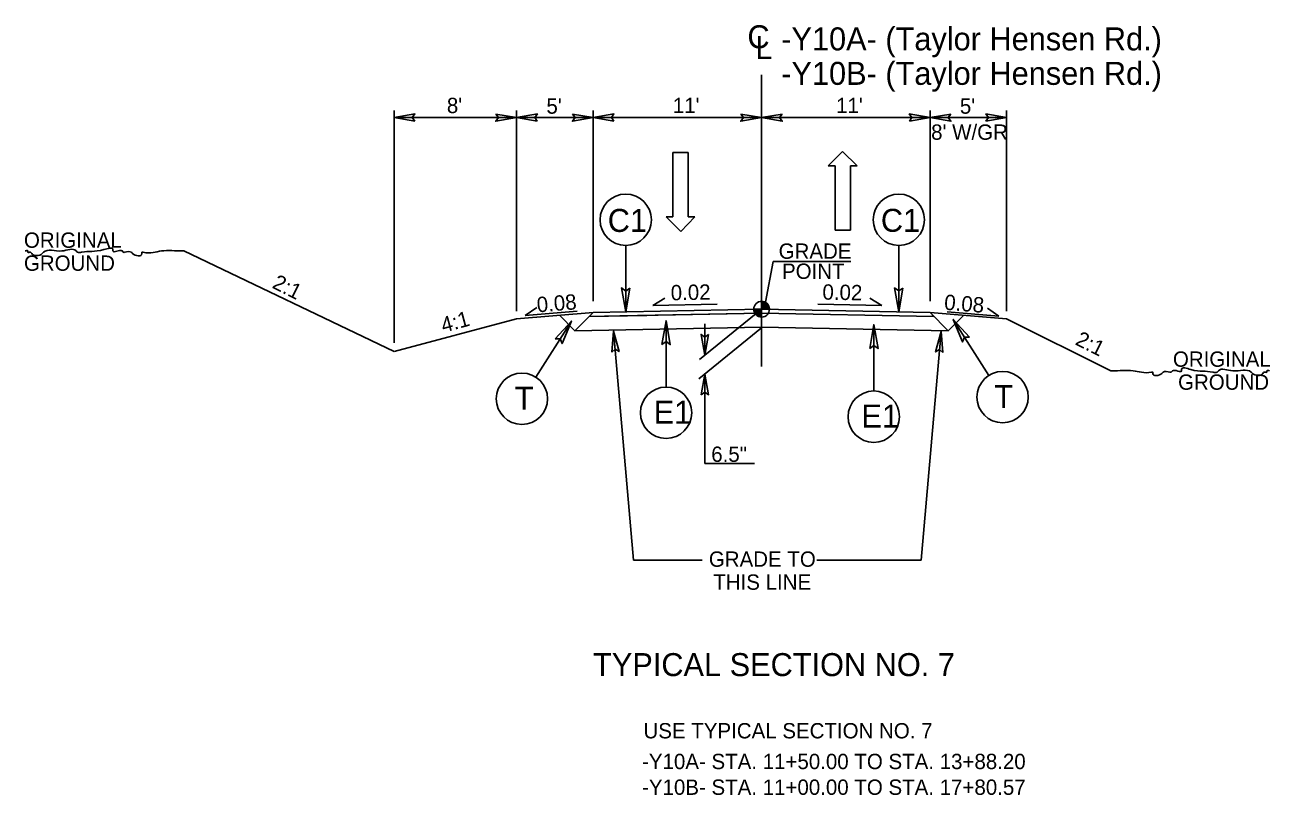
# Model space of a CAD drawing. Extents: x 18938 to 19565, y 6931 to 7973.
# Drawn here: x 19397.7 to 19479, y 7533.7 to 7584 of the extents above; entities that cross this region are included whole.
import ezdxf

# ---------------------------------------------------------------- set-up
doc = ezdxf.new("R2010")
doc.units = 0
for name, color, linetype in [('Old_Level_11', 7, 'Continuous'), ('Old_Level_2', 7, 'Continuous'), ('Prop Pavement Schedule Description CELL', 7, 'Continuous'), ('Prop Shade Medium', 7, 'Continuous'), ('Prop Terminator CELL', 7, 'Continuous'), ('Sheet Data Field CELL', 7, 'Continuous'), ('Sheet Plot Border Outside CELL', 7, 'Continuous'), ('Sheet Typical CELL', 7, 'Continuous'), ('Typical Curb CELL', 7, 'Continuous'), ('Typical Detail Wedge1 CELL', 7, 'Continuous'), ('Typical Detail Wedge2 CELL', 7, 'Continuous'), ('Typical Detail Wedge3 CELL', 7, 'Continuous'), ('Typical Hinge Slope Arterial CELL', 7, 'Continuous'), ('Typical Shoulder Slope Information CELL', 7, 'Continuous'), ('Typical Terminator CELL', 7, 'Continuous'), ('Typical Text General CELL', 7, 'Continuous'), ('Typical Text Grade Point CELL', 7, 'Continuous'), ('Typical Text ID Circle CELL', 7, 'Continuous'), ('Typical Text Label CELL', 7, 'Continuous')]:
    doc.layers.add(name, color=color, linetype=linetype)

msp = doc.modelspace()

# ---------------------------------------------------------------- linework, layer by layer
at = {"layer": 'Prop Pavement Schedule Description CELL'}
for p, q in [((19429.776, 7564.789), (19434.776, 7565.189)), ((19433.585, 7563.998), (19432.571, 7565.012)), ((19433.585, 7563.998), (19434.776, 7565.189)), ((19438.276, 7565.009), (19434.521, 7564.934)), ((19434.776, 7565.189), (19445.776, 7565.409)), ((19436.776, 7564.979), (19445.776, 7565.159)), ((19456.776, 7565.189), (19445.776, 7565.409)), ((19445.776, 7565.159), (19457.031, 7564.934)), ((19461.776, 7564.789), (19456.776, 7565.189)), ((19457.966, 7563.998), (19456.776, 7565.189)), ((19457.966, 7563.998), (19458.981, 7565.012)), ((19468.577, 7561.388), (19461.776, 7564.789)), ((19433.585, 7563.998), (19445.776, 7564.242)), ((19438.276, 7564.096), (19438.276, 7564.092)), ((19457.966, 7563.998), (19445.776, 7564.242)), ((19453.276, 7564.096), (19453.276, 7564.092))]:
    msp.add_line(p, q, dxfattribs=at)
at = {"layer": 'Prop Shade Medium'}
for p in [(19408.043, 7569.209), (19429.776, 7564.789)]:
    msp.add_line(p, (19421.776, 7562.64), dxfattribs=at)
at = {"layer": 'Sheet Data Field CELL'}
for points in [[(19423.126, 7577.681), (19421.776, 7577.914), (19423.133, 7578.154), (19422.961, 7577.914)], [(19428.426, 7578.146), (19429.776, 7577.914), (19428.418, 7577.674), (19428.591, 7577.914)], [(19431.126, 7577.681), (19429.776, 7577.914), (19431.133, 7578.154), (19430.961, 7577.914)], [(19433.426, 7578.146), (19434.776, 7577.914), (19433.418, 7577.674), (19433.591, 7577.914)], [(19436.126, 7577.681), (19434.776, 7577.914), (19436.133, 7578.154), (19435.961, 7577.914)], [(19444.416, 7578.146), (19445.766, 7577.914), (19444.409, 7577.674), (19444.581, 7577.914)], [(19447.116, 7578.146), (19445.766, 7577.914), (19447.124, 7577.674), (19446.951, 7577.914)], [(19455.426, 7577.681), (19456.776, 7577.914), (19455.418, 7578.154), (19455.591, 7577.914)], [(19458.126, 7578.146), (19456.776, 7577.914), (19458.133, 7577.674), (19457.961, 7577.914)], [(19460.426, 7577.681), (19461.776, 7577.914), (19460.418, 7578.154), (19460.591, 7577.914)], [(19435.998, 7562.614), (19436.113, 7563.979), (19436.469, 7562.647), (19436.215, 7562.799)], [(19457.606, 7562.588), (19457.492, 7563.953), (19457.134, 7562.621), (19457.389, 7562.772)], [(19442.299, 7563.754), (19442.067, 7562.404), (19441.827, 7563.762), (19442.067, 7563.589)], [(19441.835, 7559.831), (19442.067, 7561.181), (19442.307, 7559.823), (19442.067, 7559.996)]]:
    msp.add_lwpolyline(points, close=True, dxfattribs=at)
at = {"layer": 'Sheet Typical CELL'}
for p, q in [((19421.776, 7578.374), (19421.776, 7563.209)), ((19421.776, 7577.914), (19429.776, 7577.914)), ((19429.776, 7578.374), (19429.776, 7565.286)), ((19429.776, 7577.914), (19434.776, 7577.914)), ((19434.776, 7578.374), (19434.776, 7565.929)), ((19456.776, 7577.914), (19434.776, 7577.914)), ((19456.776, 7578.374), (19456.776, 7565.929)), ((19461.776, 7577.914), (19456.776, 7577.914)), ((19461.776, 7578.374), (19461.776, 7565.286)), ((19445.776, 7565.409), (19441.721, 7562.124)), ((19437.405, 7549.027), (19436.113, 7563.979)), ((19445.776, 7564.185), (19441.671, 7560.86)), ((19442.067, 7564.448), (19442.067, 7562.404)), ((19456.187, 7549.027), (19457.492, 7563.953)), ((19442.067, 7561.181), (19442.067, 7555.343)), ((19442.067, 7555.343), (19445.319, 7555.343)), ((19437.405, 7549.027), (19441.893, 7549.027)), ((19449.371, 7549.027), (19456.187, 7549.027))]:
    msp.add_line(p, q, dxfattribs=at)
at = {"layer": 'Typical Curb CELL'}
for points in [[(19397.678, 7569.209), (19397.85, 7569.209), (19397.85, 7569.124), (19398.021, 7569.124), (19398.107, 7569.038), (19398.792, 7569.038), (19398.877, 7569.124), (19400.077, 7569.209), (19401.019, 7569.209), (19401.105, 7569.124), (19401.362, 7569.124), (19402.818, 7569.295), (19403.417, 7569.295), (19403.417, 7569.209), (19404.017, 7569.209), (19404.102, 7569.124), (19404.188, 7569.124), (19404.616, 7569.124), (19404.702, 7569.038), (19405.302, 7569.038), (19405.302, 7569.124), (19405.387, 7569.124), (19406.586, 7569.209), (19407.957, 7569.209), (19408.043, 7569.209)], [(19478.941, 7561.388), (19478.77, 7561.388), (19478.77, 7561.302), (19478.599, 7561.302), (19478.513, 7561.217), (19477.828, 7561.217), (19477.742, 7561.302), (19476.543, 7561.388), (19475.601, 7561.388), (19475.515, 7561.302), (19475.258, 7561.302), (19473.802, 7561.474), (19473.202, 7561.474), (19473.202, 7561.388), (19472.603, 7561.388), (19472.517, 7561.302), (19472.432, 7561.302), (19472.003, 7561.302), (19471.918, 7561.217), (19471.318, 7561.217), (19471.318, 7561.302), (19471.233, 7561.302), (19470.033, 7561.388), (19468.663, 7561.388), (19468.577, 7561.388)]]:
    msp.add_spline(points, degree=3, dxfattribs=at)
at = {"layer": 'Typical Detail Wedge1 CELL'}
for p, q in [((19445.776, 7565.409), (19445.776, 7565.921)), ((19445.264, 7565.409), (19445.776, 7565.409)), ((19446.288, 7565.409), (19445.776, 7565.409)), ((19445.776, 7564.897), (19445.776, 7565.409)), ((19445.776, 7565.409), (19445.776, 7564.897))]:
    msp.add_line(p, q, dxfattribs=at)
for points in [[(19445.781, 7565.921), (19445.781, 7565.921), (19445.781, 7565.409)], [(19445.791, 7565.92), (19445.791, 7565.409)], [(19445.801, 7565.92), (19445.801, 7565.409)], [(19445.812, 7565.919), (19445.812, 7565.409)], [(19445.822, 7565.918), (19445.822, 7565.409)], [(19445.832, 7565.918), (19445.832, 7565.409)], [(19445.843, 7565.916), (19445.843, 7565.409)], [(19445.853, 7565.915), (19445.853, 7565.409)], [(19445.863, 7565.913), (19445.863, 7565.409)], [(19445.873, 7565.911), (19445.873, 7565.409)], [(19445.884, 7565.909), (19445.883, 7565.409)], [(19445.894, 7565.907), (19445.894, 7565.409)], [(19445.904, 7565.905), (19445.904, 7565.409)], [(19445.914, 7565.902), (19445.914, 7565.409)], [(19445.924, 7565.899), (19445.924, 7565.409)], [(19445.935, 7565.896), (19445.935, 7565.409)], [(19445.945, 7565.892), (19445.945, 7565.409)], [(19445.955, 7565.888), (19445.955, 7565.409)], [(19445.965, 7565.884), (19445.965, 7565.409)], [(19445.976, 7565.88), (19445.975, 7565.409)], [(19445.986, 7565.875), (19445.986, 7565.409)], [(19445.996, 7565.871), (19445.996, 7565.409)], [(19446.006, 7565.866), (19446.006, 7565.409)], [(19446.017, 7565.86), (19446.017, 7565.409)], [(19446.027, 7565.855), (19446.027, 7565.409)], [(19446.037, 7565.849), (19446.037, 7565.409)], [(19446.048, 7565.843), (19446.047, 7565.409)], [(19446.058, 7565.836), (19446.058, 7565.409)], [(19446.068, 7565.829), (19446.068, 7565.409)], [(19446.078, 7565.822), (19446.078, 7565.409)], [(19446.088, 7565.814), (19446.088, 7565.409)], [(19446.099, 7565.806), (19446.098, 7565.409)], [(19446.109, 7565.798), (19446.109, 7565.409)], [(19446.119, 7565.788), (19446.119, 7565.408)], [(19446.129, 7565.779), (19446.129, 7565.409)], [(19446.139, 7565.769), (19446.139, 7565.408)], [(19446.15, 7565.759), (19446.15, 7565.408)], [(19446.16, 7565.747), (19446.16, 7565.409)], [(19446.17, 7565.735), (19446.17, 7565.408)], [(19446.18, 7565.722), (19446.18, 7565.408)], [(19446.191, 7565.709), (19446.191, 7565.409)], [(19446.201, 7565.694), (19446.201, 7565.408)], [(19446.211, 7565.678), (19446.211, 7565.408)], [(19446.221, 7565.661), (19446.221, 7565.409)], [(19446.232, 7565.642), (19446.232, 7565.408)], [(19446.242, 7565.621), (19446.242, 7565.408)], [(19446.252, 7565.597), (19446.252, 7565.409)], [(19446.262, 7565.569), (19446.262, 7565.408)], [(19445.267, 7565.409), (19445.267, 7565.353)], [(19445.277, 7565.409), (19445.277, 7565.293)], [(19445.287, 7565.409), (19445.287, 7565.255)], [(19445.298, 7565.409), (19445.298, 7565.226)], [(19445.308, 7565.409), (19445.308, 7565.201)], [(19445.318, 7565.409), (19445.318, 7565.179)], [(19445.328, 7565.409), (19445.328, 7565.16)], [(19445.339, 7565.409), (19445.339, 7565.143)], [(19445.349, 7565.409), (19445.349, 7565.127)], [(19445.359, 7565.409), (19445.359, 7565.111)], [(19445.37, 7565.409), (19445.37, 7565.098)], [(19445.38, 7565.409), (19445.38, 7565.085)], [(19445.39, 7565.409), (19445.39, 7565.072)], [(19445.4, 7565.409), (19445.4, 7565.061)], [(19445.41, 7565.409), (19445.41, 7565.05)], [(19445.421, 7565.409), (19445.42, 7565.04)], [(19445.431, 7565.409), (19445.431, 7565.031)], [(19445.441, 7565.409), (19445.441, 7565.022)], [(19445.451, 7565.409), (19445.451, 7565.013)], [(19445.461, 7565.409), (19445.461, 7565.004)], [(19445.472, 7565.409), (19445.472, 7564.997)], [(19445.482, 7565.409), (19445.482, 7564.989)], [(19445.492, 7565.409), (19445.492, 7564.982)], [(19445.502, 7565.409), (19445.502, 7564.976)], [(19445.513, 7565.409), (19445.513, 7564.969)], [(19445.523, 7565.409), (19445.523, 7564.963)], [(19445.533, 7565.409), (19445.533, 7564.958)], [(19445.544, 7565.409), (19445.544, 7564.953)], [(19445.554, 7565.409), (19445.554, 7564.947)], [(19445.564, 7565.409), (19445.564, 7564.943)], [(19445.574, 7565.409), (19445.574, 7564.938)], [(19445.585, 7565.409), (19445.584, 7564.934)], [(19445.595, 7565.409), (19445.595, 7564.93)], [(19445.605, 7565.409), (19445.605, 7564.926)], [(19445.615, 7565.409), (19445.615, 7564.922)], [(19445.625, 7565.409), (19445.625, 7564.919)], [(19445.636, 7565.409), (19445.635, 7564.916)], [(19445.646, 7565.409), (19445.646, 7564.913)], [(19445.656, 7565.409), (19445.656, 7564.911)], [(19445.666, 7565.409), (19445.666, 7564.908)], [(19445.677, 7565.409), (19445.676, 7564.906)], [(19445.687, 7565.409), (19445.687, 7564.905)], [(19445.697, 7565.409), (19445.697, 7564.903)], [(19445.707, 7565.409), (19445.707, 7564.901)], [(19445.717, 7565.409), (19445.717, 7564.9)], [(19445.728, 7565.409), (19445.728, 7564.899)], [(19445.738, 7565.409), (19445.738, 7564.898)], [(19445.748, 7565.409), (19445.748, 7564.898)], [(19445.759, 7565.409), (19445.759, 7564.897)], [(19445.769, 7565.409), (19445.769, 7564.897), (19445.769, 7564.897)], [(19446.273, 7565.533), (19446.273, 7565.408)], [(19446.283, 7565.481), (19446.283, 7565.409)]]:
    msp.add_lwpolyline(points, dxfattribs=at)
msp.add_circle((19445.776, 7565.409), 0.512, dxfattribs=at)
for start, end in [(359.99048, 89.99048), (179.99048, 269.99048)]:
    msp.add_arc((19445.776, 7565.409), 0.512, start, end, dxfattribs=at)
at = {"layer": 'Typical Detail Wedge3 CELL'}
for p, q in [((19439.983, 7571.427), (19439.983, 7575.627)), ((19439.983, 7575.627), (19440.973, 7575.627)), ((19440.973, 7575.627), (19440.973, 7571.427)), ((19450.129, 7574.756), (19451.059, 7575.701)), ((19451.059, 7575.701), (19452.019, 7574.756)), ((19450.579, 7574.756), (19450.129, 7574.756)), ((19450.579, 7570.556), (19450.579, 7574.756)), ((19452.019, 7574.756), (19451.569, 7574.756)), ((19451.569, 7574.756), (19451.569, 7570.556)), ((19440.493, 7570.482), (19439.533, 7571.427)), ((19439.533, 7571.427), (19439.983, 7571.427)), ((19441.423, 7571.427), (19440.493, 7570.482)), ((19440.973, 7571.427), (19441.423, 7571.427)), ((19451.569, 7570.556), (19450.579, 7570.556))]:
    msp.add_line(p, q, dxfattribs=at)
at = {"layer": 'Typical Hinge Slope Arterial CELL'}
for p, q in [((19434.521, 7564.934), (19434.776, 7565.189)), ((19436.521, 7564.974), (19434.521, 7564.934)), ((19434.776, 7565.189), (19445.776, 7565.409)), ((19445.776, 7565.159), (19436.521, 7564.974)), ((19436.521, 7564.974), (19436.521, 7564.974)), ((19445.776, 7565.409), (19456.776, 7565.189)), ((19457.031, 7564.934), (19445.776, 7565.159)), ((19456.776, 7565.189), (19457.031, 7564.934))]:
    msp.add_line(p, q, dxfattribs=at)
at = {"layer": 'Typical Terminator CELL'}
for p, q in [((19436.899, 7569.565), (19436.899, 7565.234)), ((19454.736, 7569.57), (19454.736, 7565.239)), ((19460.614, 7561.088), (19458.287, 7564.741)), ((19431.025, 7560.978), (19433.352, 7564.631)), ((19439.533, 7560.327), (19439.533, 7564.658)), ((19453.1, 7560.072), (19453.1, 7564.403))]:
    msp.add_line(p, q, dxfattribs=at)
for centre in [(19436.899, 7571.241), (19454.736, 7571.246), (19430.125, 7559.564), (19461.514, 7559.675), (19439.533, 7558.652), (19453.1, 7558.396)]:
    msp.add_circle(centre, 1.676, dxfattribs=at)
at = {"layer": 'Typical Text General CELL'}
for points in [[(19437.166, 7566.785), (19436.899, 7565.234), (19436.623, 7566.794), (19436.899, 7566.596)], [(19455.003, 7566.791), (19454.736, 7565.239), (19454.46, 7566.799), (19454.736, 7566.601)], [(19459.346, 7563.576), (19458.287, 7564.741), (19458.893, 7563.277), (19459.019, 7563.592)], [(19432.293, 7563.466), (19433.352, 7564.631), (19432.746, 7563.167), (19432.62, 7563.482)], [(19439.266, 7563.107), (19439.533, 7564.658), (19439.809, 7563.098), (19439.533, 7563.296)], [(19452.833, 7562.851), (19453.1, 7564.403), (19453.376, 7562.843), (19453.1, 7563.041)]]:
    msp.add_lwpolyline(points, close=True, dxfattribs=at)
at = {"layer": 'Typical Text Grade Point CELL'}
for p, q in [((19438.68, 7565.649), (19439.463, 7566.122)), ((19438.68, 7565.649), (19442.869, 7565.733)), ((19453.624, 7565.649), (19449.435, 7565.733)), ((19453.624, 7565.649), (19452.841, 7566.122)), ((19430.343, 7565.009), (19431.097, 7565.529)), ((19430.343, 7565.009), (19433.729, 7565.28)), ((19461.274, 7564.965), (19457.888, 7565.236)), ((19461.274, 7564.965), (19460.521, 7565.485))]:
    msp.add_line(p, q, dxfattribs=at)
at = {"layer": 'Typical Text ID Circle CELL'}
for p, q in [((19445.776, 7580.703), (19445.766, 7577.914)), ((19445.766, 7577.914), (19445.776, 7561.672)), ((19446.026, 7565.862), (19446.521, 7568.53)), ((19451.598, 7568.529), (19446.521, 7568.53))]:
    msp.add_line(p, q, dxfattribs=at)

# ---------------------------------------------------------------- texts
at = {"layer": 'Old_Level_11'}
for s, height, p in [('TYPICAL SECTION NO. 7', 1.5, (19434.768, 7541.468)), ('USE TYPICAL SECTION NO. 7', 1, (19438.061, 7537.404))]:
    msp.add_text(s, height=height, dxfattribs=at).set_placement(p)
at = {"layer": 'Old_Level_2'}
for s, p in [('ORIGINAL', (19397.602, 7569.416)), ('GROUND', (19397.602, 7567.916))]:
    msp.add_text(s, height=1, rotation=360, dxfattribs=at).set_placement(p)
for s, p in [('ORIGINAL', (19472.634, 7561.652)), ('GROUND', (19472.97, 7560.152))]:
    msp.add_text(s, height=1, dxfattribs=at).set_placement(p)
at = {"layer": 'Prop Terminator CELL'}
for s, p in [('C1', (19435.725, 7570.452)), ('C1', (19453.562, 7570.457)), ('T', (19460.969, 7558.955)), ('E1', (19438.725, 7557.94)), ('E1', (19452.292, 7557.685))]:
    msp.add_text(s, height=1.5, dxfattribs=at).set_placement(p)
msp.add_text('T', height=1.5, rotation=360, dxfattribs=at).set_placement((19429.656, 7558.844))
at = {"layer": 'Sheet Plot Border Outside CELL'}
for s, p in [('GRADE', (19446.887, 7568.698)), ('POINT', (19447.105, 7567.387))]:
    msp.add_text(s, height=1, rotation=0.00004, dxfattribs=at).set_placement(p)
at = {"layer": 'Typical Detail Wedge2 CELL'}
for s, p in [("8'", (19425.222, 7578.203)), ("5'", (19431.722, 7578.164)), ("11'", (19439.977, 7578.203)), ("11'", (19450.641, 7578.203)), ("5'", (19458.722, 7578.164)), ("8' W/GR", (19456.846, 7576.464)), ('6.5"', (19442.486, 7555.446)), ('GRADE TO', (19442.329, 7548.602)), ('THIS LINE', (19442.62, 7547.102)), ('-Y10A- STA. 11+50.00 TO STA. 13+88.20', (19437.968, 7535.398)), ('-Y10B- STA. 11+00.00 TO STA. 17+80.57', (19437.968, 7533.72))]:
    msp.add_text(s, height=1, dxfattribs=at).set_placement(p)
at = {"layer": 'Typical Shoulder Slope Information CELL'}
for s, rotation, p in [('2:1', 333.43491, (19413.752, 7566.831)), ('4:1', 15.1346, (19424.992, 7563.865)), ('2:1', 333.43491, (19466.189, 7563.127))]:
    msp.add_text(s, height=1, rotation=rotation, dxfattribs=at).set_placement(p)
at = {"layer": 'Typical Text Grade Point CELL'}
for s, rotation, p in [('0.08', 4.5738, (19431.131, 7565.198)), ('0.02', 1.14574, (19439.848, 7565.984)), ('0.02', 358.85426, (19449.739, 7566.038)), ('0.08', 355.4262, (19457.67, 7565.379))]:
    msp.add_text(s, height=1, rotation=rotation, dxfattribs=at).set_placement(p)
at = {"layer": 'Typical Text Label CELL'}
for s, p in [('C', (19444.847, 7582.436)), ('-Y10A- (Taylor Hensen Rd.)', (19447.055, 7582.298)), ('L', (19445.363, 7581.73)), ('-Y10B- (Taylor Hensen Rd.)', (19447.055, 7580.048))]:
    msp.add_text(s, height=1.5, dxfattribs=at).set_placement(p)

doc.saveas('drawing.dxf')
